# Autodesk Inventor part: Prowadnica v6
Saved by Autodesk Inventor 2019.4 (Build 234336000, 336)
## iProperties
Created: 2020-01
Part Number: Prowadnica v6
Material: Generic
Document SubType Name: Modeling
Designer: Administrator
Density: 1 g/cm^3
Appearance: Default
Author: Administrator
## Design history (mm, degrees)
feature "Body1"
feature "Body2"
body "Solid1"
body "Solid2"
